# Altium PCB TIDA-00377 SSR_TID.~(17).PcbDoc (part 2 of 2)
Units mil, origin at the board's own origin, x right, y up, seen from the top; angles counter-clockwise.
Board outline 4300 x 2000 mil, 2 copper layers (Layer 1 - Top Layer, Layer 2 - Bottom Layer), stack 62 mil thick; 114 components, 37 nets, 228 pads, 275 vias.
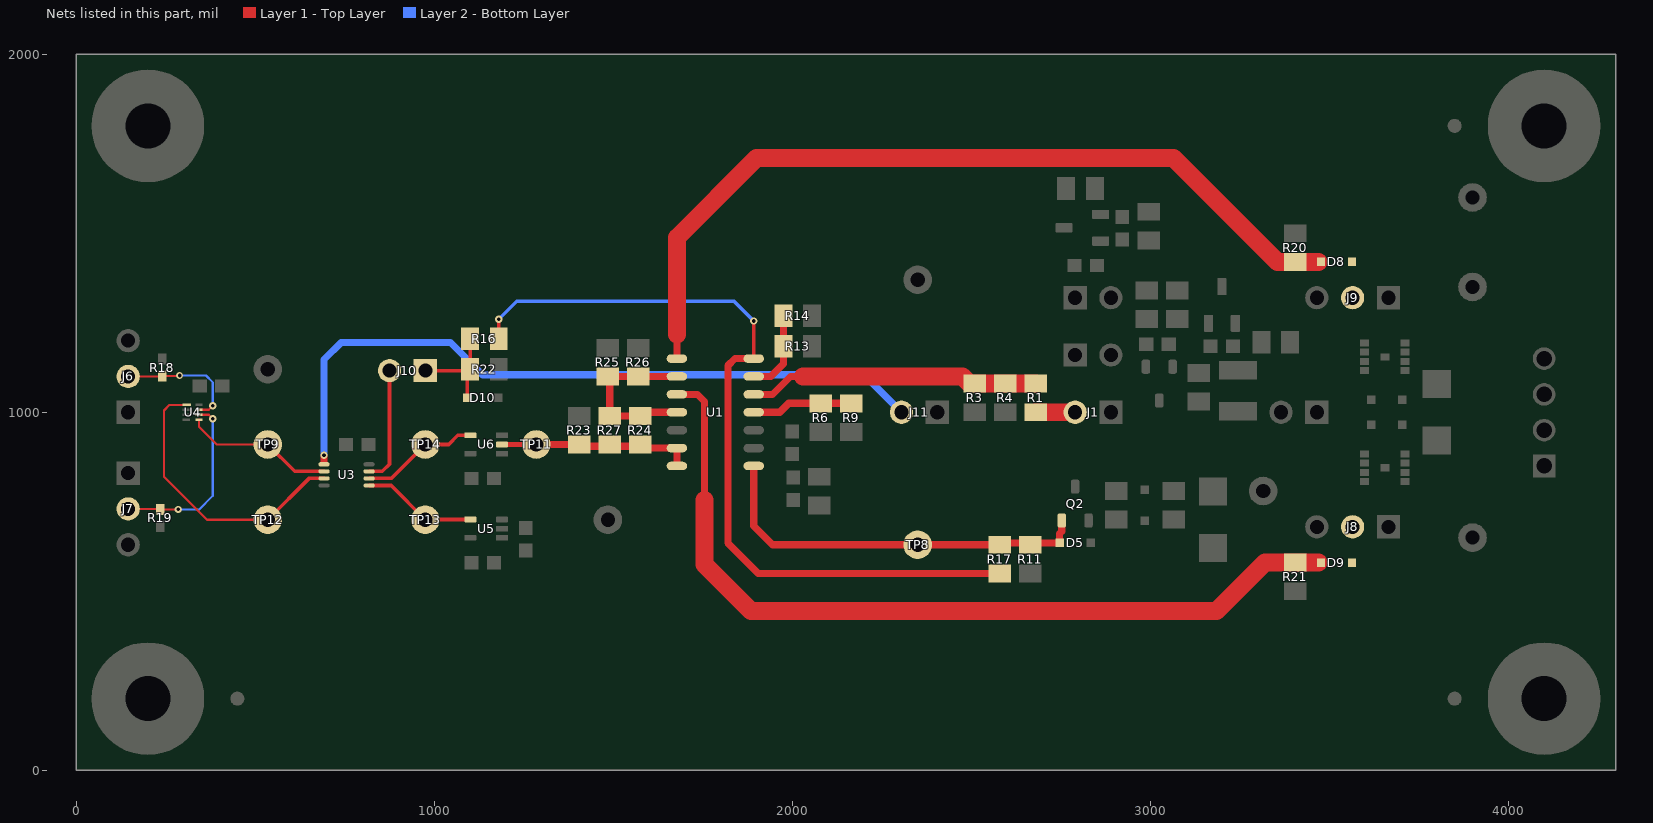
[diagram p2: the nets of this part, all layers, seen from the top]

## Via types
v1: diameter 20, hole 10, Layer 1 - Top Layer to Layer 2 - Bottom Layer, tented both sides, 275 vias

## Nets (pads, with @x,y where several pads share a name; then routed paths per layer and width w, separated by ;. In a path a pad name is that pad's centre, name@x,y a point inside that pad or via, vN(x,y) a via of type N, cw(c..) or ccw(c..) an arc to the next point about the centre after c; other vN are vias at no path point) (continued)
NetD5_1: D5.1 Q2.1 R11.2 R17.2 TP8.1 U1.1 | length 1110.8
  Layer 1 - Top Layer w20: U1.1@1892.28,850 1892.28,682.72 1945,630 TP8.1@2350,630 R17.2@2580,630 2585,635 D5.1@2746.69,635 2746.69,661.7 2752.59,667.6 Q2.1@2752.59,697.76
NetD8_1: D8.1 J9.2
NetD8_2: D8.2 R20.2 U1.8 | length 2342.2
  Layer 1 - Top Layer w20: U1.8@1677.72,1150 1677.72,1217.28
  Layer 1 - Top Layer w50: 1677.72,1217.28 1677.72,1487.72 1900,1710 3065,1710 3355,1420 R20.2@3405,1420 D8.2@3470,1420
NetD9_1: D9.1 J8.2
NetD9_2: D9.2 R21.2 U1.10 | length 2365.3
  Layer 1 - Top Layer w20: U1.10@1677.72,1050 1735,1050 1755,1030 1755,755
  Layer 1 - Top Layer w50: 1755,755 1755,575 1885,445 3185,445 3320,580 R21.2@3405,580 D9.2@3470,580
NetD10_1: D10.1 J10.1 R16.1 R22.1 | length 289.9
  Layer 1 - Top Layer w10: J10.1@975,1116.5 R22.1@1096.5,1116.5 ; D10.1@1091.69,1040 1091.69,1111.69 R22.1@1096.5,1116.5 ; R16.1@1100,1205 R22.1@1100,1120 R22.1@1096.5,1116.5
NetJ1_2: J1.2 R1.1 | length 110
  Layer 1 - Top Layer w50: R1.1@2680,1000 J1.2@2790,1000
NetJ10_2: J10.2 U3.7 | length 326.9
  Layer 1 - Top Layer w10: U3.7@817.99,834.84 854.84,834.84 875,855 J10.2@875,1116.5
NetJ11_2: J11.2 U3.1 | length 2000.7
  Layer 1 - Top Layer w20: U3.1@692.01,860 v1(692.01,880)
  Layer 2 - Bottom Layer w20: v1(692.01,880) 692.01,1147.01 740,1195 1045,1195 1135,1105 2200,1105 J11.2@2305,1000
NetR1_2: R1.2 R3.2 R4.1 U1.5 | length 816.7
  Layer 1 - Top Layer w20: U1.5@1892.28,1050 1945,1050 1995,1100 2030,1100
  Layer 1 - Top Layer w50: 2030,1100 2475,1100 2495,1080 R3.2@2510,1080 R1.2@2680,1080
NetR6_2: R6.2 R9.1 U1.4 | length 278.1
  Layer 1 - Top Layer w20: U1.4@1892.28,1000 1965,1000 1990,1025 R6.2@2075,1025 ; R6.2@2080,1025 R9.1@2165,1025
NetR13_2: R13.2 R14.1 U1.6 | length 227.2
  Layer 1 - Top Layer w20: U1.6@1892.28,1100 1940,1100 1975,1135 R13.2@1975,1185 R14.1@1975,1265
NetR16_2: R16.2 R17.1 U1.7 | length 2286.6
  Layer 1 - Top Layer w10: R16.2@1180,1205 v1(1180,1260) ; U1.7@1892.28,1150 v1(1892.28,1255)
  Layer 1 - Top Layer w20: U1.7@1892.28,1150 1840,1150 1820,1130 1820,635 1905,550 R17.1@2580,550
  Layer 2 - Bottom Layer w10: v1(1180,1260) 1230,1310 1837.28,1310 v1(1892.28,1255)
NetR23_2: R23.2 R24.1 R27.1 TP11.1 U1.13 U1.14 U6.2 | length 540.5
  Layer 1 - Top Layer w15: U6.2@1189.29,910 TP11.1@1285,910 TP11.1@1290,910
  Layer 1 - Top Layer w20: TP11.1@1290,910 R23.2@1405,910 R23.2@1410,910 ; R23.2@1410,905 1490,905 1570,905 1575,900 U1.13@1677.72,900 U1.14@1677.72,850
NetR24_2: R24.2 R25.2 R26.1 R27.2 U1.9 U1.11 | length 489.6
  Layer 1 - Top Layer w20: U1.11@1677.72,1000 1580,1000 1570,990 R27.2@1490,990 1490,1100 R26.1@1570,1100 U1.9@1677.72,1100
NetTP9_1: TP9.1 U3.2 U4.5 | length 420.5
  Layer 1 - Top Layer w6: U4.5@342.72,979.33 342.72,960 392.72,910 TP9.1@535,910
  Layer 1 - Top Layer w10: TP9.1@535,910 610.16,834.84 U3.2@692.01,834.84
NetTP12_1: TP12.1 U3.3 U4.1 | length 800.2
  Layer 1 - Top Layer w6: U4.1@309.25,1020.67 260.67,1020.67 245,1005 245,820 365,700 TP12.1@535,700
  Layer 1 - Top Layer w10: TP12.1@535,700 650.16,815.16 U3.3@692.01,815.16
NetTP13_1: TP13.1 U3.5 U5.4 | length 322.5
  Layer 1 - Top Layer w10: U3.5@817.99,795.47 879.53,795.47 TP13.1@975,700 975.59,700.59 U5.4@1100.71,700.59
NetTP14_1: TP14.1 U3.6 U6.4 | length 332.6
  Layer 1 - Top Layer w10: U3.6@817.99,815.16 880.16,815.16 TP14.1@975,910 1040,910 1065.59,935.59 U6.4@1100.71,935.59
OFF#: J7.2 R19.1 U4.6 | length 511.3
  Layer 1 - Top Layer w6: J7.2@145,730 233.62,730 R19.1@235,728.62 v1(285,728.62) ; U4.6@342.72,993.11 369.99,993.11 v1(381.4,981.7)
  Layer 2 - Bottom Layer w6: v1(285,728.62) 343.62,728.62 381.4,766.4 v1(381.4,981.7)
ON#: J6.2 R18.1 U4.7 | length 353
  Layer 1 - Top Layer w6: J6.2@145,1100 R18.1@238.62,1100 ; R18.1@240,1101.38 v1@290,1101.38 ; U4.7@342.72,1006.89 369.99,1006.89 v1(381.4,1018.3)
  Layer 2 - Bottom Layer w6: v1(288.62,1102.76) 362.24,1102.76 381.4,1083.6 v1(381.4,1018.3)
pads on no net: FID1.1 FID2.1 FID3.1 H1.1 H2.1 H3.1 H4.1 SH-J1.0 SH-J2.0 SH-J3.0 SH-J4.0 SH-J6.0 SH-J7.0 SH-J8.0 SH-J9.0 SH-J10.0 SH-J11.0 U4.3 U5.1 U6.1

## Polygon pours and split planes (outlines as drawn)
GND on Layer 1 - Top Layer "Layer 1 - Top Layer - GND" (solid, remove dead copper, pour order 2): 20,20 4280,20 4280,1980 20,1980
GND on Layer 2 - Bottom Layer "Layer 2 - Bottom Layer - GND" (solid, remove dead copper, pour order 4): 20,20 4280,20 4280,1980 20,1980

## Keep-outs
Keep-Out Layer:
  text ".Layer_Name" at 577,-858.49 h60

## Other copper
Layer 1 - Top Layer:
  pour cut-out: 2960,1375 2825,1375 2804.65,1395.35 2804.65,1669.65 2815,1680 2885,1680 2960,1605
  pour cut-out: 3462.7,539.65 3634.65,539.65 3655,560 3640.85,574.15 3484.15,574.15 3462.7,552.7
  pour cut-out: 2740,1050 2940,1050 2940,950 2740,950
  pour cut-out: 2255,1050 2455,1050 2455,950 2255,950
  pour cut-out: 825,1166.5 1025,1166.5 1025,1066.5 825,1066.5
  pour cut-out: 95,580 95,780 208.19,780 208.19,580
  pour cut-out: 95,1050 95,1250 195,1250 195,1050
  region net GND: 2795,1660 2795,1500 2690,1500 2690,1660
  region net GND: 3193,1145 3193,1080 3360,1080 3360,1145
  pour cut-out: 3475.35,1455 3660,1455 3670,1445 3485.35,1445
  pour cut-out: 2945,1380.35 2815.35,1380.35 2815,1380 2815,1345 2945,1345
  pour cut-out: 2540,960 2650,960 2650,1040 2540,1040
  pour cut-out: 1085.94,723.8 1166.2,723.8 1170,720 1240,720 1240,645 1221.2,626.2 1103.8,626.2 1085.94,644.06
  pour cut-out: 1093.8,861.2 1080,875 1080,952.85 1085.94,958.8 1261.2,958.8 1270,950 1270,875 1256.2,861.2
  pour cut-out: 1044.51,815 1004.98,854.53 910.47,854.53 885,880 885,955 895.47,965.47 1067.59,965.47 1077.08,955.98 1077.08,837.08 1055,815
  pour cut-out: 185,945 255,945 255,1030 315,1030 315,1085 185,1085
  region net GND: 317.87,974.96 317.87,982.13 317,983 292,983 280,995 269,995 264,990 264,982 280,966
  pour cut-out: 3025,1150 3130,1150 3130,1220 3270,1220 3270,1335 3020,1335
  pour cut-out: 2770,485 2770,604.69 2773.5,608.19 2806.49,608.19 2860,661.7 2860,760 2730,760 2725,755 2725,485
  pour cut-out: 645,780 835,780 835,905.49 781.81,905.49 781.81,890 725,890 725,905.49 645,905.49
  pour cut-out: 1680.35,779.65 1620,840 1620,1230 1645,1255 1955,1255 2035,1175 2035,785 2029.65,779.65
  pour cut-out: 3611,604 3655,560 4135,560 4220,645 4220,1360 4125,1455 3660,1455 3611,1406
  pour cut-out: 2742.52,1207.48 2742.52,1277.52 2765,1300 2950,1300 2950,1230 2927.48,1207.48
  pour cut-out: 2726.5,1040.35 2726.5,1118.92 2742.52,1134.94 3045.06,1134.94 3055,1125 3055,1050 3035,1030 2736.85,1030
  pour cut-out: 3120.63,726.7 2953.3,726.7 2945,735 2945,760 3115,760 3120.63,754.37
  pour cut-out: 3514.71,710 3514.71,759.71 3540,785 3615,785 3615,710
  region net HV1: 3695,1015 3630,1080 3630,1350 3695,1415 4115,1415 4180,1350 4180,1080 4115,1015
  region net HV2: 3695,985 3630,920 3630,650 3695,585 4115,585 4180,650 4180,920 4115,985
  region net NetD1_1: 3635,1045 3625,1055 3435,1055 3425,1045 3425,955 3435,945 3625,945 3635,955
  region net GND: 3611,1133 3512,1133 3505,1140 3505,1200 3515,1210 3611,1210
  region net GND: 3611,823 3512,823 3505,830 3505,890 3515,900 3611,900
  region net NetD9_1: 3600,710 3600,580 3585,565 3545,565 3530,580 3530,710 3545,725 3585,725
  region net NetD8_1: 3530,1290 3530,1420 3545,1435 3585,1435 3600,1420 3600,1290 3585,1275 3545,1275
  region net NetC1_2: 3400,1045 3390,1055 2865,1055 2855,1045 2855,955 2865,945 3390,945 3400,955
  region net 10V: 1960,955 1980,975 2115,975 2115,870 2110,865 2060,865 2055,870 2055,905 2040,920 1985,920 1960,945
  region net GND: 2200,910 2185,895 2130,895 2130,975 2200,975
  region net GND: 3365,1155 3475,1155 3475,1235 3365,1235
  region net GND: 3245,1324.68 3245,1369.68 3235,1379.68 3165,1379.68 3155,1369.68 3155,1324.68
  region net 10V: 3370,530 3370,425 3380,415 3430,415 3440,425 3440,530
  region net 10V: 3440,1470 3440,1575 3430,1585 3380,1585 3370,1575 3370,1470
  region net 10V: 2025,1150 2130,1150 2140,1160 2140,1210 2130,1220 2025,1220
  region net 10V: 1520,1150 1520,1255 1510,1265 1460,1265 1450,1255 1450,1150
  region net 10V: 2630,510 2745,510 2755,520 2755,570 2745,580 2630,580
  region net 10V: 2835,766.07 2835,811.07 2825,821.07 2755,821.07 2745,811.07 2745,766.07
  region net GND: 2025,1235 2130,1235 2140,1245 2140,1295 2130,1305 2025,1305
  region net GND: 1605,1150 1605,1255 1595,1265 1545,1265 1535,1255 1535,1150
  region net GND: 3030,726.7 3030,621.7 3040,611.7 3090,611.7 3100,621.7 3100,726.7
  region net GND: 2560,1030 2560,925 2570,915 2620,915 2630,925 2630,1030
  region net 3.3V: 1440,960 1440,1065 1430,1075 1380,1075 1370,1065 1370,960
  region net 3.3V: 2040,770 2040,665 2050,655 2100,655 2110,665 2110,770
  text ".Layer_Name" at 577,-858.49 h60
Layer 2 - Bottom Layer:
  pour cut-out: 2255,952.11 2255,1050 2455,1050 2455,952.11
  pour cut-out: 825,1068.61 825,1166.5 1025,1166.5 1025,1068.61
  pour cut-out: 190,580 95,580 95,780 190,780
  pour cut-out: 190,1050 95,1050 95,1250 190,1250
  pour cut-out: 3515,630 3715,630 3715,730 3515,730
  pour cut-out: 3505,950 3315,950 3315,1050 3505,1050
  pour cut-out: 3515,1270 3715,1270 3715,1370 3515,1370
  pour cut-out: 4030,780 4170,780 4170,1215 4030,1215
  pour cut-out: 2960,956 2956,952 2790.11,952 2742.11,1000 2742.11,1159.36 2665.44,1236.03 2665.44,1290.4 2742.52,1367.48 2917.52,1367.48 2940,1345 2940,1055 2960,1035
  text ".Layer_Name" at 577,-858.49 h60

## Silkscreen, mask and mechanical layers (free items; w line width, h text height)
Top Overlay:
  text "GND" at 3850,1675 h50
  text "GND" at 2300,1445 h50
  text "HV1" at 3860,1425 h50
  text "GND" at 485,1195 h50
  text "ON" at 75,1065 h50 r90
  text "OFF" at 75,685 h50 r90
  text "HV2" at 3860,490 h50
  text "ISBA-EVM-00377" at 2650,190 h100
  text "Rev. A" at 2650,90 h100
  text ".Layer_Name" at 577,-858.49 h60
Bottom Overlay:
  text ".Layer_Name" at 577,-858.49 h60
Top Paste:
  text ".Layer_Name" at 577,-858.49 h60
Bottom Paste:
  text ".Layer_Name" at 577,-858.49 h60
Top Solder:
  text ".Layer_Name" at 577,-858.49 h60
  text ".Layer_Name" at 577,-858.49 h60
Bottom Solder:
  text ".Layer_Name" at 577,-858.49 h60
Drill Guide:
  text ".Layer_Name" at 577,-858.49 h60
M1 Board Outline:
  the board outline again, w10
  text ".Layer_Name" at 577,-858.49 h60
M2 Board Dimensions:
  rectangle: 125,-400 500,-275
  rectangle: 0,-275 125,-150
  lines w7: 0,-275 1000,-275 ; 125,-400 125,-150 ; 250,-400 250,-150 ; 500,-400 500,-150 ; 750,-400 750,-150 ; 0,-400 0,-150 1000,-150 1000,-400 0,-400
  text ".Layer_Name" at 577,-858.49 h60
M3 3D STEP Top:
  text ".Layer_Name" at 577,-858.49 h60
M4 3D STEP Bottom:
  text ".Layer_Name" at 577,-858.49 h60
M5 Assembly Top:
  lines w10: -292,-930.17 6308,-930.17 ; -292,-726.83 6310,-726.83 ; -292,-523.5 -292,-1133.5 3713,-1133.5 6310,-1133.5 6310,-523.5 -291.5,-523.5 -291.5,-1133.5 1284,-1133.5 ; 2173,-1133.5 2173,-523.5 ; 3440,-726.83 3440,-523.5 ; 4280,-726.83 4280,-523.5 ; 4902,-1140 4902,-937.17
  text "COMPONENTS MARKED 'DNP' SHOULD NOT BE POPULATED." at 1153.5,-318.5 h60
  text "ASSEMBLY VARIANT:" at 1153,-434 h60
  text ".VariantName" at 2189,-434 h60
  text "PCB VIEWED FROM TOP SIDE" at -228.5,-655.67 h60
  text "BOARD #:" at 2248,-655.67 h60
  text ".PRJ_Number" at 2793.5,-655.67 h60
  text "REV:" at 3638,-655.67 h60
  text ".PCB_Rev" at 3929.5,-655.67 h60
  text "SVN REV:" at 4476,-655.67 h60
  text ".VersionControl_RevNumber" at 4982,-655.67 h60
  text "TID #:" at 2248,-859 h60
  text ".TID" at 2793.5,-859 h60
  text "PLOT NAME =" at -228.5,-1064.34 h60
  text ".plot_File_Name" at 577,-1064.34 h60
  text "GENERATED    :" at 2250,-1064.34 h60
  text ".Print_Date" at 3119.5,-1064.34 h60
  text ".Print_Time" at 3848.5,-1064.34 h60
  text "TEXAS INSTRUMENTS" at 5113,-1064.34 h60
M6 Assembly Bottom:
  lines w10: -292.5,-727.33 6309.5,-727.33 ; -290.5,-930.67 6309.5,-930.67 ; 1115.5,-1140.5 1115.5,-937.67 ; 1737.5,-727.33 1737.5,-524 ; 2577.5,-727.33 2577.5,-524 ; 3844.5,-1134 3844.5,-524 ; 4733.5,-1134 6309,-1134 6309,-524 -292.5,-524 -292.5,-1134 2304.5,-1134 6309.5,-1134 6309.5,-524
  text "COMPONENTS MARKED 'DNP' SHOULD NOT BE POPULATED." at 6102,-318 h60
  text ".VariantName" at 5058,-434 h60
  text "ASSEMBLY VARIANT:" at 6097,-434 h60
  text ".VersionControl_RevNumber" at 1035.5,-656.17 h60
  text "SVN REV:" at 1541.5,-656.17 h60
  text ".PCB_Rev" at 2088,-656.17 h60
  text "REV:" at 2379.5,-656.17 h60
  text ".PRJ_Number" at 3224,-656.17 h60
  text "BOARD #:" at 3769.5,-656.17 h60
  text "PCB VIEWED FROM BOTTOM SIDE" at 6246,-656.17 h60
  text ".TID" at 3224,-859.5 h60
  text "TID #:" at 3769.5,-859.5 h60
  text "TEXAS INSTRUMENTS" at 904.5,-1064.84 h60
  text ".Print_Time" at 2169,-1064.84 h60
  text ".Print_Date" at 2898,-1064.84 h60
  text "GENERATED    :" at 3767.5,-1064.84 h60
  text ".plot_File_Name" at 5440.5,-1064.84 h60
  text "PLOT NAME =" at 6246,-1064.84 h60
M9 Title Sheet:
  drawing of 1178 lines, arcs and shapes, not listed
  text "1" at 739.84,8036.5 h70
  text "2" at 3235.5,8036.5 h70
  text "3" at 5724.84,8036.5 h70
  text "4" at 8231.51,8036.5 h70
  text "5" at 10730.5,8036.5 h70
  text "6" at 13235.5,8036.5 h70
  text "A" at -416.5,6893.5 h70
  text "A" at 14383.5,6893.5 h70
  text "B" at -416.5,4513.5 h70
  text "B" at 14383.5,4513.5 h70
  text "C" at -416.5,2138.5 h70
  text "C" at 14383.5,2138.5 h70
  text "PROJECT TITLE:" at 11343.5,277.5 h45
  text ".PRJ_Title" at 11393.5,144.17 h70
  text "DESIGNED FOR:" at 11343.5,-23.5 h45
  text ".PRJ_Customer" at 11393.5,-163.5 h70
  text "D" at -416.5,-231.5 h70
  text "D" at 14383.5,-231.5 h70
  text "FILE NAME:" at 11343.5,-323.5 h45
  text ".PCB_File_Name_No_Path" at 11393.5,-443.5 h70
  text "Texas Instruments (TI) and/or its licensors do not warrant the accuracy or completeness of this specification" at 6374,-605.34 h45
  text "ENGINEER:" at 11343.5,-613.5 h45
  text "LAYOUT BY:" at 12848.5,-613.5 h45
  text "or any information contained therein. TI and/or its licensors do not warrant that this design will meet" at 6329.01,-718 h45
  text ".PRJ_Engineer" at 11393.5,-768.49 h70
  text ".PCB_Layout" at 12899,-768.49 h70
  text "JMM" at 12851,-801 h100
  text "s  o  l  u  t  i  o  n  s" at 13709,-804 h68
  text "the specifications, will be suitable for your application or fit for any particular purpose, or will operate in" at 6329.01,-830.67 h45
  text ".Layer_Name" at 577,-858.49 h60
  text "ALTIUM DESIGNER VERSION:" at 12848.5,-923.5 h45
  text "an implementation. TI and/or its licensors do not warrant that the design is production worthy. You should" at 6329.01,-943.33 h45
  text "completely validate and test your design implementation to confirm the system functionality for your application." at 6374,-1056 h45
  text ".print_Scale" at 11393.5,-1056.83 h70
  text ".Application_BuildNumber" at 12899,-1056.83 h70
  text "1" at 739.84,-1263.5 h70
  text "2" at 3235.5,-1263.5 h70
  text "3" at 5724.84,-1263.5 h70
  text "4" at 8231.51,-1263.5 h70
  text "5" at 10730.5,-1263.5 h70
  text "6" at 13235.5,-1263.5 h70
M10 Fab Notes:
  drawing of 173 lines, arcs and shapes, not listed
  text "DESIGN INFORMATION" at 12377.02,6201 h60
  text "MIN. TRACK WIDTH:" at 11732.46,6021 h60
  text "6" at 12828.7,6021 h60
  text "MIL" at 12983.46,6021 h60
  text "MIN. CLEARANCE:" at 11732.46,5889 h60
  text "0.2" at 12768.7,5889 h60
  text "mm" at 12983.46,5889 h60
  text "MIN. VIA PAD SIZE:" at 11732.46,5757 h60
  text "20" at 12798.71,5757 h60
  text "MIL" at 12983.46,5757 h60
  text "0.05mm (2MIL)" at 12427.46,5615.29 h60
  text "MINIMUM ANNULAR RING" at 11403.23,5611 h60
  text "EXTERNAL" at 13135.46,5611 h60
  text "PER" at 11603.23,5493 h60
  text "IPC-D-275 CLASS 2 LEVEL C" at 11823.23,5493 h60
  text "MIL, HOLES" at 13311.46,5380.71 h60
  text "+/-" at 12919,5380 h60
  text "+/-" at 13773,5380 h60
  text "REGISTRATION TOLERANCES:" at 11403.23,5375 h60
  text "METAL" at 12603,5375 h60
  text "5" at 13179.2,5375 h60
  text "3" at 14012.2,5375 h60
  text "MIL" at 14128.46,5375 h60
  text "+/-" at 13773,5262 h60
  text "HOLE SIZE TOLERANCE (UNLESS OTHERWISE SPECIFIED):" at 11403.23,5257 h60
  text "3" at 14012.2,5257 h60
  text "MIL" at 14128.46,5257 h60
  text "MATERIAL:" at 11328.46,5047.54 h60
  text "FR-4 High Tg" at 12314.9,4907.21 h60
  text "FR-408" at 11749.46,4898.64 h60
  text "OTHER" at 13237.46,4898.64 h60
  text "X" at 12160,4895 h60
  text "62 MIL (1.6mm) +/-10%" at 12069.56,4735.92 h60
  text "THICKNESS:" at 11403.23,4731.64 h60
  text "X" at 11941.4,4731.64 h60
  text "OTHER" at 13354.46,4731.64 h60
  text "TOLERANCE:" at 11403.23,4573.64 h60
  text "X" at 12242.53,4573.64 h60
  text "ANSI IPC-6012 TYPE 3 CLASS 2" at 12429.48,4573.64 h60
  text "OTHER +/-" at 12429.46,4417.64 h60
  text "BOW & TWIST:" at 11403.23,4260.64 h60
  text "X" at 12242.53,4260.64 h60
  text "ANSI IPC-6012 TYPE 3 CLASS 2" at 12429.48,4260.64 h60
  text "OTHER +/-" at 12429.46,4102.13 h60
  text "DRILLING:" at 11328.46,3963.64 h60
  text "REFERENCE:" at 11403.23,3846.64 h60
  text "X" at 12051.46,3846.64 h60
  text "AS SHOWN" at 12238.46,3846.64 h60
  text "X" at 12952.46,3846.64 h60
  text "NC_DRILL FILES" at 13089.46,3846.64 h60
  text "PTH MIN COPPER THICKNESS:" at 11403.23,3688.64 h60
  text "X" at 12753.46,3688.64 h60
  text "1MIL" at 12890.46,3688.64 h60
  text "OTHER" at 13387.46,3688.64 h60
  text "BOARD FINISH:" at 11328.46,3529.64 h60
  text "SILKSCREEN:" at 11483.68,3411.64 h60
  text "X" at 12432.46,3411.64 h60
  text "TOP" at 12558.46,3411.64 h60
  text "BOTTOM" at 13069.46,3411.64 h60
  text "SILKSCREEN COLOR:" at 11483.68,3244.64 h60
  text "X" at 12431.42,3244.64 h60
  text "WHITE" at 12558.46,3244.64 h60
  text "OTHER" at 13069.46,3244.64 h60
  text "GREEN" at 12689.46,3085.44 h60
  text "OTHER" at 13307.46,3085.44 h60
  text "X" at 12561,3084 h60
  text "SOLDER RESIST COLOR:" at 11483.68,3074.64 h60
  text "MATTE" at 12689.46,2915.44 h60
  text "SEMI-GLOSS" at 13307,2914.8 h60
  text "X" at 13140.7,2912.9 h60
  text "IMMERSION GOLD (ENIG)" at 12389.46,2726.92 h60
  text "ENEPIG" at 13727,2723.64 h60
  text "SURFACE FINISH:" at 11328.46,2722.64 h60
  text "X" at 12202.51,2722.64 h60
  text "IMM. TIN/SILVER OR EQUIV" at 11658,2565.64 h60
  text "OTHER" at 13089.46,2565.64 h60
  text "ARRAY/PANEL:" at 11328.46,2386.64 h60
  text "CUT AND TRIM PER M1 BOARD OUTLINE" at 12389.46,2382.35 h60
  text "N.C. ROUTE" at 12389.46,2230.64 h60
  text "X" at 13068.46,2230.64 h60
  text "V. SCORE" at 13255.46,2230.64 h60
  text "CERTIFICATION:" at 11328.46,2093.64 h60
  text "MATERIALS AND WORKMANSHIP FOR ALL PCBS" at 12053.46,2093.64 h60
  text "TO MEET OR EXCEED THE REQUIREMENTS OF:" at 12053.46,1995.64 h60
  text "X" at 11679.96,1859.13 h60
  text "ANSI IPC-A-600F CLASS ->" at 11818.96,1859.13 h60
  text "X" at 13458.02,1859.13 h60
  text "2" at 13576.96,1859.14 h60
  text "1" at 13261.96,1857.64 h60
  text "3" at 13930.96,1857.64 h60
  text "X" at 12494.02,1699.64 h60
  text "RoHS" at 12630.96,1699.64 h60
  text "OTHER" at 13275.36,1699.64 h60
  text "PER ORDER" at 13672.42,1699.64 h60
  text "ALL BOARDS MUST MEET OR EXCEED UL94-V0 REQUIREMENTS." at 11356,1534 h60
  text "PCB MUST BEAR THE UL94V-0 UL REGISTERED MATERIAL ID NUMBER" at 11356,1414 h60
  text "ADDITIONAL REQUIREMENTS:" at 11328.46,1240.64 h60
  text "MICROSECTION:" at 11403.23,1125.64 h60
  text "YES" at 12308.96,1125.64 h60
  text "REQUIRED" at 13170.46,969.49 h60
  text "BARE BOARD ELEC. TEST:" at 11403.23,966.64 h60
  text "NONE" at 12708.96,966.64 h60
  text "X" at 13043.46,966.64 h60
  text "PER ORDER" at 13762.46,966.64 h60
  text ".Layer_Name" at 577,-858.49 h60
M11 Gerber Information:
  lines w10: -292,-930.17 6308,-930.17 ; -292,-726.83 6310,-726.83 ; -292,-523.5 -292,-1133.5 3713,-1133.5 6310,-1133.5 6310,-523.5 -291.5,-523.5 -291.5,-1133.5 1284,-1133.5 ; 2173,-1133.5 2173,-523.5 ; 3440,-726.83 3440,-523.5 ; 4280,-726.83 4280,-523.5 ; 4902,-1140 4902,-937.17
  text "ALL ARTWORK VIEWED FROM TOP SIDE" at -228.5,-655.67 h60
  text "BOARD #:" at 2248,-655.67 h60
  text ".PRJ_Number" at 2793.5,-655.67 h60
  text "REV:" at 3638,-655.67 h60
  text ".PCB_Rev" at 3929.5,-655.67 h60
  text "SVN REV:" at 4476,-655.67 h60
  text ".VersionControl_RevNumber" at 4982,-655.67 h60
  text "LAYER NAME =" at -228.5,-858.49 h60
  text "TID #:" at 2248,-859 h60
  text ".TID" at 2793.5,-859 h60
  text "PLOT NAME =" at -228.5,-1064.34 h60
  text ".plot_File_Name" at 577,-1064.34 h60
  text "GENERATED    :" at 2250,-1064.34 h60
  text ".Print_Date" at 3119.5,-1064.34 h60
  text ".Print_Time" at 3848.5,-1064.34 h60
  text "TEXAS INSTRUMENTS" at 5113,-1064.34 h60
M12 Stackup:
  drawing of 339 lines, arcs and shapes, not listed
  text "Layer" at 8200,7840 h60
  text "Name" at 8609.91,7840 h60
  text "Material" at 10019.5,7840 h60
  text "Thickness" at 10879.27,7840 h60
  text "Constant" at 11529.1,7840 h60
  text "Board Layer Stack" at 12098.97,7840 h60
  text "Board Layer Stack" at 13218.65,7840 h60
  text "1" at 8200,7720 h60
  text "Top Overlay" at 8609.91,7720 h60
  text "2" at 8200,7600 h60
  text "Top Solder" at 8609.91,7600 h60
  text "Solder Resist" at 10019.5,7600 h60
  text "0.40mil" at 10879.27,7600 h60
  text "3.5" at 11529.1,7600 h60
  text "3" at 8200,7480 h60
  text "Layer 1 - Top Layer" at 8609.91,7480 h60
  text "Copper" at 10019.5,7480 h60
  text "1.40mil" at 10879.27,7480 h60
  text "4" at 8200,7360 h60
  text "Dielectric1" at 8609.91,7360 h60
  text "370HR" at 10019.5,7360 h60
  text "59.20mil" at 10879.27,7360 h60
  text "4.8" at 11529.1,7360 h60
  text "5" at 8200,7240 h60
  text "Layer 2 - Bottom Layer" at 8609.91,7240 h60
  text "Copper" at 10019.5,7240 h60
  text "1.40mil" at 10879.27,7240 h60
  text "6" at 8200,7120 h60
  text "Bottom Solder" at 8609.91,7120 h60
  text "Solder Resist" at 10019.5,7120 h60
  text "0.40mil" at 10879.27,7120 h60
  text "3.5" at 11529.1,7120 h60
  text "7" at 8200,7000 h60
  text "Bottom Overlay" at 8609.91,7000 h60
  text ".Layer_Name" at 577,-858.49 h60
M13 Component Bodies Top:
  text ".Layer_Name" at 577,-858.49 h60
M14 Component Bodies Bottom:
  text ".Layer_Name" at 577,-858.49 h60
M15 Courtyards Top:
  text ".Layer_Name" at 577,-858.49 h60
M16 Courtyards Bottom:
  text ".Layer_Name" at 577,-858.49 h60
Drill Drawing:
  circle w10: c7628.9,1592.78 r13.28
  circle w10: c7628.9,1592.78 r22.14
  circle w10: c7628.9,1393.54 r22.14
  lines w10: 7606.76,1172.15 7651.04,1172.15 7651.04,1216.43 7606.76,1216.43 7606.76,1172.15 ; 7606.76,1293.91 7628.9,1271.77 7651.04,1293.91 7628.9,1316.05 7606.76,1293.91 ; 7606.76,1482.09 7617.83,1482.09 7617.83,1471.02 7639.97,1471.02 7639.97,1482.09 7651.04,1482.09 7651.04,1504.23 7639.97,1504.23 7639.97,1515.3 7617.83,1515.3 7617.83,1504.23 7606.76,1504.23 7606.76,1482.09 ; 7615.62,1181.01 7642.18,1181.01 7642.18,1207.57 7615.62,1207.57 7615.62,1181.01
  lines w12: 7566,1142.27 11147.58,1142.27 ; 7566,1640.38 11147.58,1640.38 ; 7881.63,1042.64 7881.63,1740 ; 8198.82,1042.64 8198.82,1740 ; 8820.56,1042.64 8820.56,1740 ; 9064.88,1042.64 9064.88,1740 ; 9425.22,1042.64 9425.22,1740 ; 10603.38,1042.64 10603.38,1740 ; 7566,1042.64 11147.58,1042.64 11147.58,1740 7566,1740 7566,1042.64
  text "Symbol" at 7625.77,1670.26 h72
  text "Quantity" at 7911.52,1670.26 h72
  text "Finished Hole Size" at 8228.7,1670.26 h72
  text "Plated" at 8850.45,1670.26 h72
  text "Hole Type" at 9094.77,1670.26 h72
  text "Drill Layer Pair" at 9455.11,1670.26 h72
  text "Hole Tolerance" at 10633.26,1670.26 h72
  text "275" at 7911.52,1570.64 h60
  text "10.00mil (0.254mm)" at 8228.7,1570.64 h60
  text "PTH" at 8850.45,1570.64 h60
  text "Round" at 9094.77,1570.64 h60
  text "Layer 1 - Top Layer - Layer 2 - Bottom Layer" at 9455.11,1570.64 h60
  text "24" at 7911.52,1471.02 h60
  text "39.37mil (1.000mm)" at 8228.7,1471.02 h60
  text "PTH" at 8850.45,1471.02 h60
  text "Round" at 9094.77,1471.02 h60
  text "Layer 1 - Top Layer - Layer 2 - Bottom Layer" at 9455.11,1471.02 h60
  text "13" at 7911.52,1371.4 h60
  text "40.00mil (1.016mm)" at 8228.7,1371.4 h60
  text "PTH" at 8850.45,1371.4 h60
  text "Round" at 9094.77,1371.4 h60
  text "Layer 1 - Top Layer - Layer 2 - Bottom Layer" at 9455.11,1371.4 h60
  text "4" at 7911.52,1271.77 h60
  text "43.31mil (1.100mm)" at 8228.7,1271.77 h60
  text "PTH" at 8850.45,1271.77 h60
  text "Round" at 9094.77,1271.77 h60
  text "Layer 1 - Top Layer - Layer 2 - Bottom Layer" at 9455.11,1271.77 h60
  text "4" at 7911.52,1172.15 h60
  text "125.98mil (3.200mm)" at 8228.7,1172.15 h60
  text "PTH" at 8850.45,1172.15 h60
  text "Round" at 9094.77,1172.15 h60
  text "Layer 1 - Top Layer - Layer 2 - Bottom Layer" at 9455.11,1172.15 h60
  text "320 Total" at 7911.52,1072.53 h60
  text ".Layer_Name" at 577,-858.49 h60

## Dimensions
0,-400 to 1000,-400 on M2 Board Dimensions
0,0 to 4300,0 on M2 Board Dimensions
0,0 to 0,2000 on M2 Board Dimensions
